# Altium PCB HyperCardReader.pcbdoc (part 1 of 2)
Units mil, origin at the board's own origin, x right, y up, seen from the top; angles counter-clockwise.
Board outline 2181.35 x 1859.05 mil, 2 copper layers (Top Layer, Bottom Layer); 44 components, 43 nets, 186 pads, 102 vias.
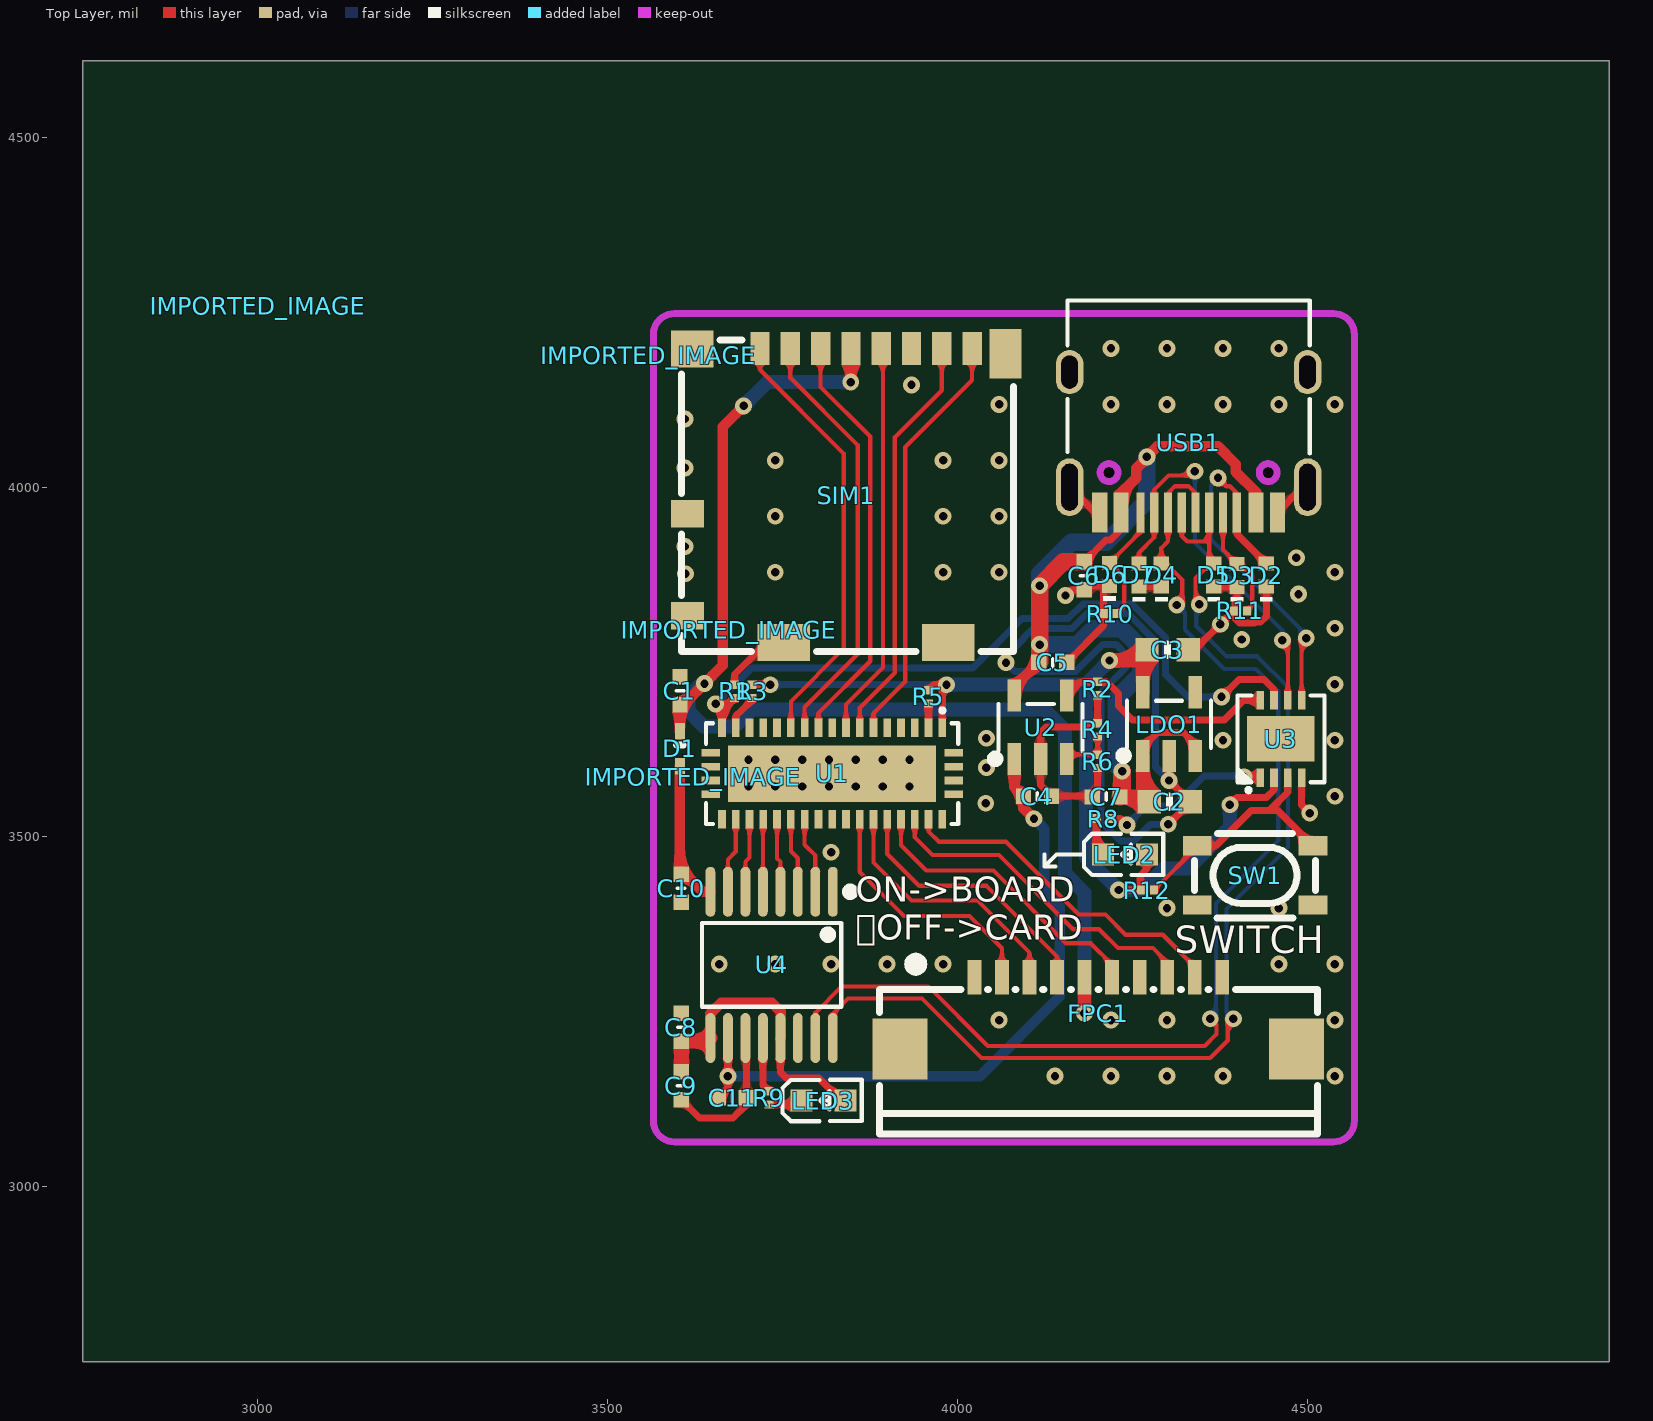
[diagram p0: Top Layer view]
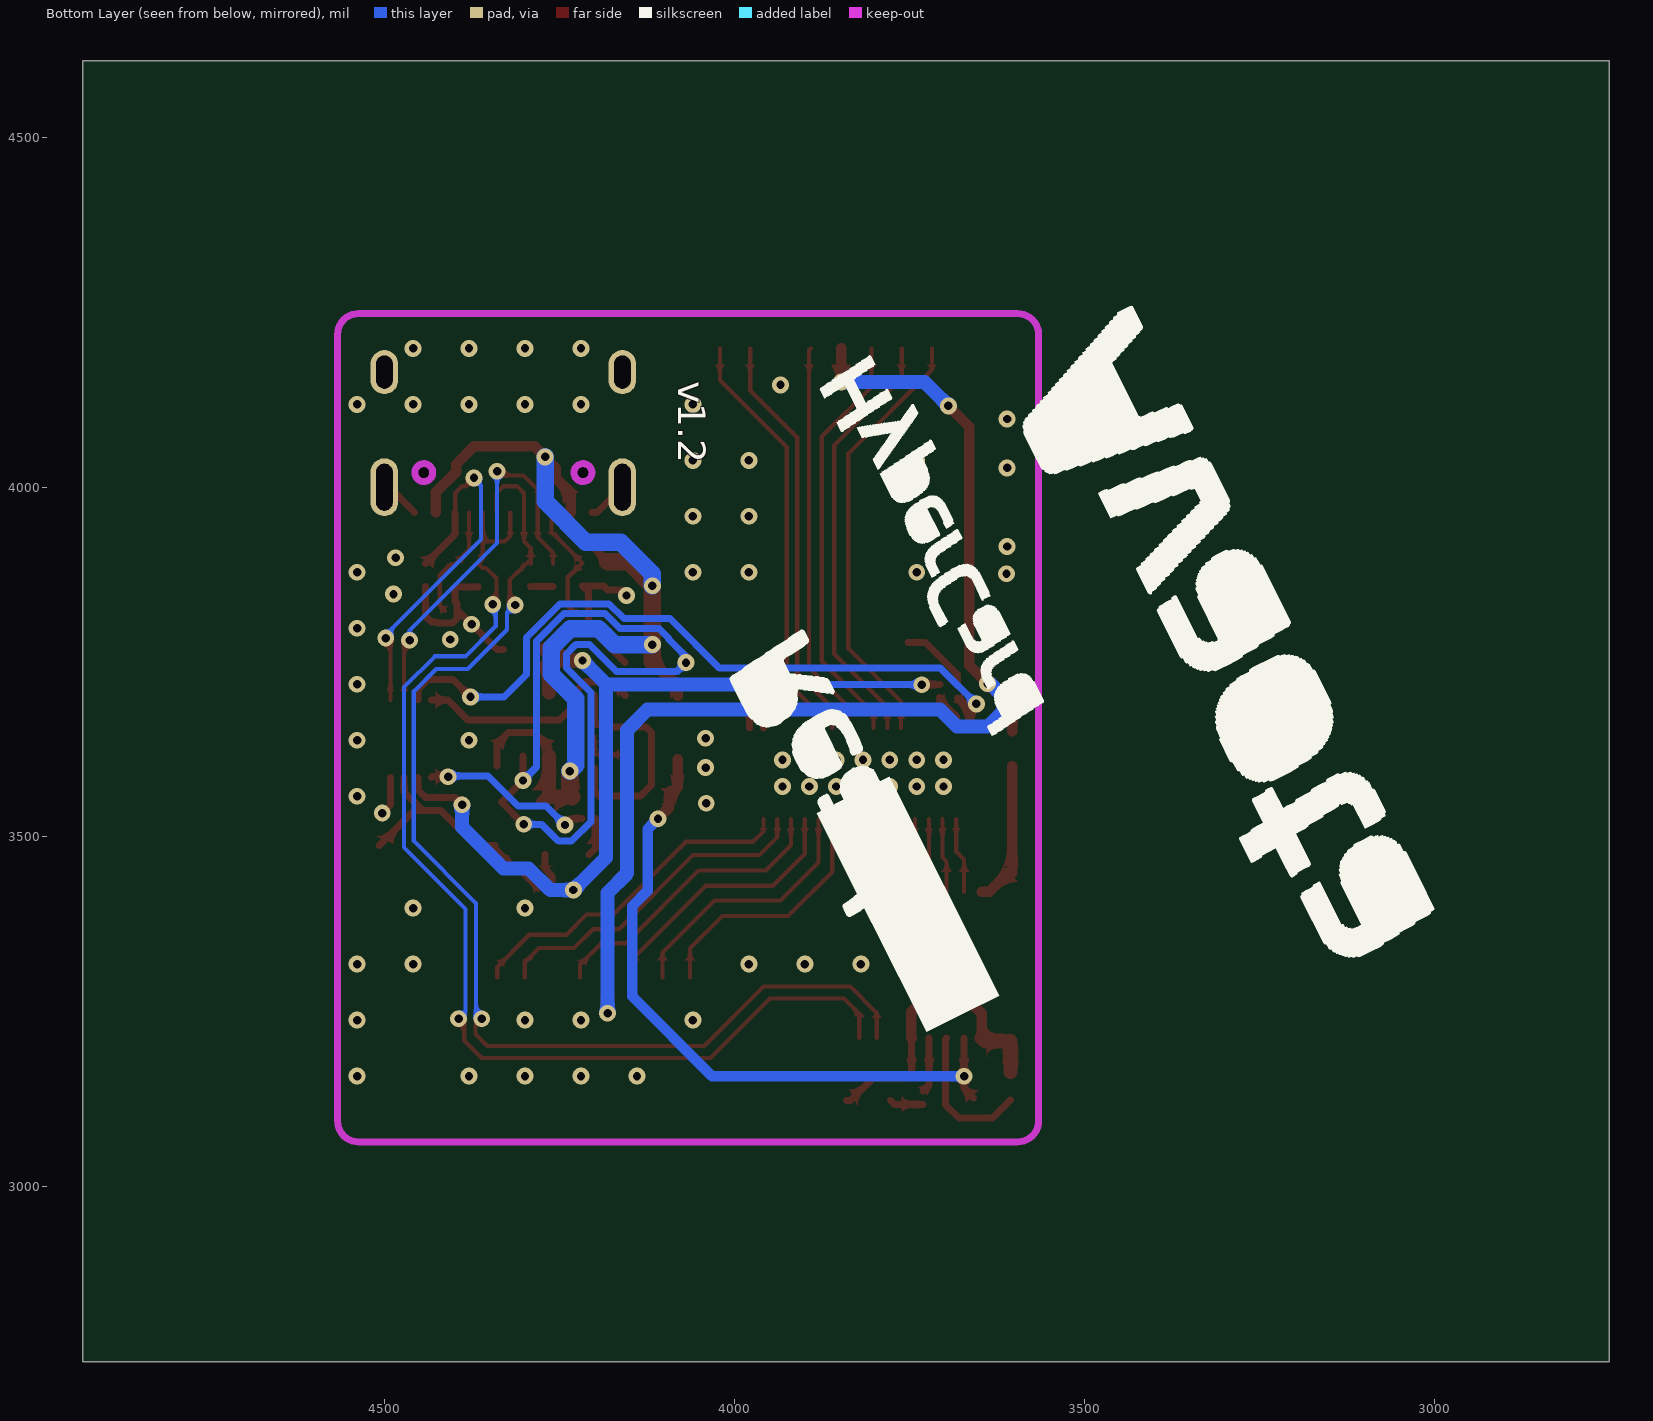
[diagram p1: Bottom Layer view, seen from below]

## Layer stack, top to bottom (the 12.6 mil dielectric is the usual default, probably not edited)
Top Layer: signal copper (thickness not stored)
Dielectric: dielectric 12.6, FR-4, Dk 4.8
Bottom Layer: signal copper (thickness not stored)

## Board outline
4931.35,2750 2750,2750 2750,4609.05 4931.35,4609.05

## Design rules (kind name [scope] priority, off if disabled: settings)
Clearance copperThickness1oz [All] p1: gap=7 ignorepadtopadclearanceinfootprint=FALSE except(4: Track-Track; 6: Track-SMDPad SMDPad-SMDPad Track-THPad SMDPad-THPad THPad-THPad Track-Via SMDPad-Via THPad-Via Via-Via Track-Fill SMDPad-Fill THPad-Fill Via-Fill Fill-Fill SMDPad-Region THPad-Region Via-Region Fill-Region Region-Region Track-Poly SMDPad-Poly THPad-Poly Via-Poly Fill-Poly Poly-Poly Track-Text SMDPad-Text THPad-Text Via-Text Fill-Text Region-Text Poly-Text Text-Text; 6.9: Track-Hole SMDPad-Hole THPad-Hole Via-Hole Fill-Hole Region-Hole Poly-Hole Text-Hole Sheet-Hole; 11.8: Track-Region Region-Poly Track-Sheet SMDPad-Sheet THPad-Sheet Via-Sheet Fill-Sheet Region-Sheet Poly-Sheet Text-Sheet)
Clearance copperThickness2oz [All] p1: gap=7 ignorepadtopadclearanceinfootprint=FALSE except(6: Track-SMDPad SMDPad-SMDPad Track-THPad SMDPad-THPad THPad-THPad Track-Via SMDPad-Via THPad-Via Via-Via Track-Fill SMDPad-Fill THPad-Fill Via-Fill Fill-Fill SMDPad-Region THPad-Region Via-Region Fill-Region Region-Region Track-Poly SMDPad-Poly THPad-Poly Via-Poly Fill-Poly Poly-Poly Track-Text SMDPad-Text THPad-Text Via-Text Fill-Text Region-Text Poly-Text Text-Text; 6.9: Track-Hole SMDPad-Hole THPad-Hole Via-Hole Fill-Hole Region-Hole Poly-Hole Text-Hole Sheet-Hole; 8: Track-Track; 11.8: Track-Region Region-Poly Track-Sheet SMDPad-Sheet THPad-Sheet Via-Sheet Fill-Sheet Region-Sheet Poly-Sheet Text-Sheet)
DiffPairsRouting differentialPair [All] p1: maxuncoupledlength=10 minlimit=0 maxlimit=5.9843 mostfreqgap=5.9843 toplayer_minwidth=5 toplayer_prefwidth=10 toplayer_maxwidth=100 bottomlayer_minwidth=5 bottomlayer_prefwidth=10 bottomlayer_maxwidth=100
PasteMaskExpansion pasteMaskExpansion [All] p1: expansion=0
PlaneConnect innerPlane [All] p1: planeconnectstyle=Relief reliefexpansion=20 reliefentries=4 reliefconductorwidth=10 reliefairgap=10
PolygonConnect copperRegion [All] p1: connectstyle=Relief reliefentries=4 reliefconductorwidth=10 polygonreliefangle="90 Angle" airgapwidth=10
RoutingVias viaSize [All] p1: viastyle="Through Hole" holewidth=12.0078 minholewidth=11.811 maxholewidth=248.0314 width=24.0158 minwidth=19.685 maxwidth=393.7008
SolderMaskExpansion solderMaskExpansion [All] p1: useseparateexpansions=TRUE expansion=2.0079 expansionbottom=2.0079
Width copperThickness1oz [All] p1: maxlimit=100 minlimit=5 preferedwidth=10
Width copperThickness2oz [All] p1: maxlimit=100 minlimit=8 preferedwidth=10

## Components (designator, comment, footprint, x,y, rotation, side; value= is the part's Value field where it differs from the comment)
C1 "CAP_0402" c0402-nsk 3603.35,3709 r270 top
C2 "CAP_0603" C0603-NSK 4303.35,3550 r180 top
C3 "CAP_0603" C0603-NSK 4300.35,3767.54 r180 top
C4 "CAP_0402" c0402-nsk 4114.36,3558.28 r180 top
C5 "CAP_0402" c0402-nsk 4136.36,3749.28 r180 top
C6 "CAP_0402" c0402-nsk 4181.35,3873 r90 top
C7 "CAP_0402" c0402-nsk 4212.35,3557 r0 top
C8 "CAP_0402" c0402-nsk 3605.35,3228 r270 top
C9 "CAP_0402" c0402-nsk 3605.35,3144 r90 top
C10 "CAP_0402" c0402-nsk 3605.25,3426.67 r90 top
C11 "CAP_0402" c0402-nsk 3678.35,3127 r180 top
D1 "B5819WT_C2997265" "SOD-523_L1.2-W0.8-LS1.6-RD-1 NSK" 3603.35,3626 r270 top
D2 "0402ESDA-05N" d0402 4441.35,3874 r90 top
D3 "0402ESDA-05N" d0402 4399.44,3873.72 r90 top
D4 "0402ESDA-05N" d0402 4291.35,3874 r90 top
D5 "0402ESDA-05N" d0402 4366.35,3874 r90 top
D6 "0402ESDA-05N" d0402 4217.35,3875 r90 top
D7 "0402ESDA-05N" d0402 4259.35,3874 r90 top
FPC1 "AFA01-S10FCC-00" FPC-SMD_AFA01-S10FCC-00 4201.35,3248 r0 top
IMPORTED_IMAGE "IMPORTED_IMAGE" IMPORTED_IMAGE 3000,4258.92 r0 top
IMPORTED_IMAGE "IMPORTED_IMAGE" IMPORTED_IMAGE 3557.69,4188.12 r0 top
IMPORTED_IMAGE "IMPORTED_IMAGE" IMPORTED_IMAGE 3621.76,3586.01 r0 top
IMPORTED_IMAGE "IMPORTED_IMAGE" IMPORTED_IMAGE 3672.82,3796.23 r0 top
LDO1 "ME6211C33M5G-N" SOT-23-5_L3.0-W1.7-P0.95-LS2.8-BL 4302.35,3661 r0 top
LED2 "LED_0603-R" LED_0603 4241.35,3475 r0 top
LED3 "LED_0603-R" LED_0603 3810.47,3123.31 r0 top
R1 "Res_0201" "r0201 nsk" 3681.35,3708 r90 top
R2 "Res_0201" "r0201 nsk" 4200.35,3712 r90 top
R3 "Res_0201" "r0201 nsk" 3706.35,3708 r90 top
R4 "Res_0201" "r0201 nsk" 4200.35,3653 r90 top
R5 "Res_0201" "r0201 nsk" 3958.35,3700 r90 top
R6 "Res_0201" "r0201 nsk" 4200.35,3608 r90 top
R8 "Res_0201" "r0201 nsk" 4208.35,3526 r0 top
R9 "Res_0201" "r0201 nsk" 3730.35,3127 r90 top
R10 "Res_0201" "r0201 nsk" 4218.35,3819 r0 top
R11 "Res_0201" "r0201 nsk" 4404.35,3823 r0 top
R12 "Res_0201" "r0201 nsk" 4271.35,3424 r0 top
SIM1 "1040310811" SIM-SMD_8P-1040310811 3841.35,3988 r180 top
SW1 "SKRPACE010" KEY-SMD_4P-L4.2-W3.2-P2.20-LS4.6 4425.35,3445 r0 top
U1 "TS3DV642A0RUAR" WFQFN-42_L9.0-W3.5-P0.50-BL-EP 3821.04,3590.48 r180 top
U2 "SY6280AAC_C55136" SOT-23-5_L3.0-W1.7-P0.95-LS2.8-BL 4118.77,3656.53 r0 top
U3 "STC8G1K08-36I-DFN8" DFN-8_L3.0-W3.0-P0.50-BL-EP 4462.35,3640 r0 top
U4 "GL823K-HCY04" SSOP-16_L4.9-W3.9-P0.64-LS6.0-BL 3734.35,3317 r180 top
USB1 "TYPEC-304-BCP16" USB-C-SMD_TYPEC-304-BCP16-1 4330.35,4064 r180 top

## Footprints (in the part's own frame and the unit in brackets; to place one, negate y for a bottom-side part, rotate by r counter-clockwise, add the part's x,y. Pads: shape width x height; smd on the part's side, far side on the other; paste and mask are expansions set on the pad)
c0402-nsk [mil]
  rect 22x22 smd: 1(-19.99,0) 2(20.01,0)
  silkscreen extent 0,-5 0,6
C0603-NSK [mm]
  rect 0.85x0.85 smd: 1(-0.75,0) 2(0.75,0)
  silkscreen extent 0,-0.21 0,0.21
d0402 [mil]
  rect 19.89x21.68 smd: 1(-16.4,0) 2(16.4,0)
  silkscreen extent -37,-9 -31,9
DFN-8_L3.0-W3.0-P0.50-BL-EP [mm]
  rect 0.28x0.665 smd: 1(-0.75,-1.407) 2(-0.25,-1.407) 3(0.25,-1.407) 4(0.75,-1.407) 5(0.75,1.407) 6(0.25,1.407) 7(-0.25,1.407) 8(-0.75,1.407)
  rect 2.45x1.65 smd: 9(0,0)
  silkscreen extent -1.58,-1.93 1.58,1.58
FPC-SMD_AFA01-S10FCC-00 [mm]
  rect 0.5x1.25 smd: 1(-4.5,1.3) 2(-3.5,1.3) 3(-2.501,1.3) 4(-1.5,1.3) 5(-0.501,1.3) 6(0.499,1.3) 7(1.5,1.3) 8(2.499,1.3) 9(3.5,1.3) 10(4.499,1.3)
  rect 2x2.2 smd: 11(-7.2,-1.3) 12(7.2,-1.3)
  silkscreen extent -7.94,-4.39 7.95,0.86
IMPORTED_IMAGE [mil]
KEY-SMD_4P-L4.2-W3.2-P2.20-LS4.6 [mm]
  rect 1.05x0.7 smd: 1(-2.1,1.075) 2(2.1,1.075) 3(-2.1,-1.075) 4(2.1,-1.075)
  silkscreen extent -2.2,-1.55 2.2,1.52
LED_0603 [mil]
  rect 31.5x31.5 smd: 1(-33.5,-0.4) 2(29.5,-0.2)
  silkscreen extent -61,-30 53,30
"r0201 nsk" [mil]
  rect 11.93x12.76 smd: 1(-9.51,0) 2(9.51,0)
SIM-SMD_8P-1040310811 [mm]
  rect 0.7x1.2 smd: 1(3.138,-5.337) 2(2.037,-5.337) 3(0.938,-5.337) 4(-0.162,-5.337) 5(-1.263,-5.337) 6(-2.363,-5.337) 7(-3.462,-5.337) 8(-4.562,-5.337)
  rect 1.17x1.8 smd: 9(-5.773,-5.138)
  rect 1.55x1.35 smd: 10(5.598,-5.313)
  rect 1.2x1 smd: 11(5.773,0.663) 12(5.773,4.363)
  rect 1.9x1.35 smd: 13(2.273,5.337) 14(-3.697,5.337)
  silkscreen extent -6.07,-5.64 5.99,5.67
"SOD-523_L1.2-W0.8-LS1.6-RD-1 NSK" [mm]
  rect 0.6x0.36 smd: 1(-0.635,0) 2(0.635,0)
  silkscreen extent -0.13,-0.13 -0.13,0.13
SOT-23-5_L3.0-W1.7-P0.95-LS2.8-BL [mm]
  rect 0.49x1.157 smd: 1(-0.95,-1.154) 2(0,-1.154) 3(0.95,-1.154)
  rect 0.49x1.175 smd: 4(0.95,1.154) 5(-0.95,1.154)
  silkscreen extent -1.8,-1.29 1.53,0.85
SSOP-16_L4.9-W3.9-P0.64-LS6.0-BL [mil]
  oval 14x71.45 smd: 1(-87.5,-104.52) 2(-62.5,-104.52) 3(-37.5,-104.52) 4(-12.5,-104.52) 5(12.5,-104.52) 6(37.5,-104.52) 7(62.5,-104.52) 8(87.5,-104.52) 9(87.5,104.52) 10(62.5,104.52) 11(37.5,104.52) 12(12.5,104.52) 13(-12.5,104.52) 14(-37.5,104.52) 15(-62.5,104.52) 16(-87.5,104.52)
  silkscreen extent -118,-110 100,60
USB-C-SMD_TYPEC-304-BCP16-1 [mm]
  oval 1x2.1 hole 0.6 slot 1.7 at 90 deg: 12(-4.32,1.633) 13(4.32,1.633)
  oval 1x1.6 hole 0.6 slot 1.2 at 90 deg: 14(-4.32,-2.547) 15(4.32,-2.547)
  rect 0.55x1.45 smd: A1B12(-3.225,2.547) A4B9(-2.45,2.547) B1A12(3.225,2.547) B4A9(2.45,2.547)
  rect 0.3x1.45 smd: A5(-1.25,2.547) A6(-0.25,2.547) A7(0.25,2.547) A8(1.25,2.547) B5(1.75,2.547) B6(0.75,2.547) B7(-0.75,2.547) B8(-1.75,2.547)
  Multi-Layer board cut-out: -3.215,1.102 -3.169,0.943 -3.051,0.826 -2.89,0.784 -2.729,0.826 -2.611,0.943 -2.565,1.102 -2.565,1.102 -2.611,1.262 -2.729,1.379 -2.89,1.421 -3.051,1.379 -3.169,1.262 -3.215,1.102
  Multi-Layer board cut-out: 2.565,1.102 2.611,0.943 2.729,0.826 2.89,0.784 3.051,0.826 3.169,0.943 3.215,1.102 3.215,1.102 3.169,1.262 3.051,1.379 2.89,1.421 2.729,1.379 2.611,1.262 2.565,1.102
  Multi-Layer keep-out circle w0.254: c-2.89,1.102 r0.325
  Multi-Layer keep-out circle w0.254: c2.89,1.102 r0.325
  silkscreen extent -4.4,-5.15 4.4,0.41
WFQFN-42_L9.0-W3.5-P0.50-BL-EP [mm]
  rect 0.28x0.665 smd: 1(-3.998,-1.658) 2(-3.498,-1.658) 3(-2.998,-1.658) 4(-2.498,-1.658) 5(-1.998,-1.658) 6(-1.498,-1.658) 7(-0.998,-1.658) 8(-0.498,-1.658) 9(0.002,-1.658) 10(0.502,-1.658) 11(1.002,-1.658) 12(1.502,-1.658) 13(2.002,-1.658) 14(2.502,-1.658) 15(3.002,-1.658) 16(3.502,-1.658) 17(4.002,-1.658) 22(4.002,1.658) 23(3.502,1.658) 24(3.002,1.658) 25(2.502,1.658) 26(2.002,1.658) 27(1.502,1.658) 28(1.002,1.658) 29(0.502,1.658) 30(0.002,1.658) 31(-0.498,1.658) 32(-0.998,1.658) 33(-1.498,1.658) 34(-1.998,1.658) 35(-2.498,1.658) 36(-2.998,1.658) 37(-3.498,1.658) 38(-3.998,1.658)
  rect 0.665x0.28 smd: 18(4.41,-0.75) 19(4.41,-0.25) 20(4.41,0.25) 21(4.41,0.75) 39(-4.405,0.75) 40(-4.405,0.25) 41(-4.405,-0.25) 42(-4.405,-0.75)
  rect 7.55x2.05 smd: 43(0.002,0)
  silkscreen extent -4.57,-2.36 4.58,1.83

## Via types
v1: diameter 24.02, hole 12.01, Top Layer to Bottom Layer, 102 vias

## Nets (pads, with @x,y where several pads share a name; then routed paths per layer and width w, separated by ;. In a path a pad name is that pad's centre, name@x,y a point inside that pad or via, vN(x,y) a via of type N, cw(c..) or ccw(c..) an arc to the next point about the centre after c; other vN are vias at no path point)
$1N1961: R4.1 R6.2 U2.3 | length 72.8
  Top Layer w6: U2.3@4156.17,3611.11 4162.57,3617.51 R6.2@4200.35,3617.51 R4.1@4200.35,3643.49
$1N4375: LED3.1 R9.1 | length 48.9
  Top Layer w10: R9.1@3730.35,3117.49 3771.55,3117.49 LED3.1@3776.97,3122.91
$1N4433: LED2.1 R8.1 | length 55.1
  Top Layer w10: R8.1@4198.84,3526 4198.84,3483.61 LED2.1@4207.85,3474.6
CC1: D3.2 R11.2 USB1.A5 | length 164.9
  Top Layer w6: USB1.A5@4379.56,3963.7 4379.56,3910.01 4380.24,3909.33 4380.91,3909.33 4386.18,3904.07 4386.18,3903.39 D3.2@4399.44,3890.12 4405.23,3890.12 4421.35,3874 4421.35,3830.49 R11.2@4413.86,3823
CC2: D6.2 R10.2 USB1.B5 | length 176.4
  Top Layer w6: R10.2@4227.86,3819 4238.35,3829.49 4238.35,3871.09 4231.91,3877.53 4231.22,3877.53 D6.2@4217.35,3891.4 4261.45,3935.5 USB1.B5@4261.45,3963.7
CPUX-RX: D2.2 U3.5 USB1.B8 | length 534.9
  Top Layer w6: v1(4372.35,4013) 4384.12,4001.23 4389.19,4001.23 4399.25,3991.17 USB1.B8@4399.25,3963.7 ; U3.5@4491.88,3695.41 4491.88,3777.53 v1(4498.35,3784)
  Top Layer w10: USB1.B8@4399.25,3963.7 4399.25,3932.5 D2.2@4441.35,3890.4
  Bottom Layer w6: v1(4372.35,4013) 4372.35,4012 4362.35,4002 4362.35,3925 4498.35,3789 v1(4498.35,3784)
CPUX-TX: D7.2 U3.6 USB1.A8 | length 565.8
  Top Layer w6: D7.2@4259.35,3890.4 4259.35,3906 4281.14,3927.79 USB1.A8@4281.14,3963.7 4281.14,3995.79 4301.84,4016.49 4333.38,4016.49 v1(4339.38,4022.49) ; v1(4464.35,3781) 4472.19,3773.16 U3.6@4472.19,3695.41
  Bottom Layer w6: v1(4339.38,4022.49) 4339.35,3920.14 4464.35,3795.14 v1(4464.35,3781)
EN: R5.1 U1.2 | length 34.9
  Top Layer w10: R5.1@3958.35,3690.49 3958.74,3690.1 U1.2@3958.74,3655.74
GND: C1.1 C2.1 C3.1 C4.1 C5.1 C6.1 C7.1 C8.1 C9.1 C10.1 C11.1 D2.1 D3.1 D4.1 D5.1 D6.1 D7.1 FPC1.1 FPC1.7 FPC1.11 FPC1.12 LDO1.2 R1.2 R2.1 R4.2 R6.1 R10.1 R11.1 SIM1.6 SIM1.9 SIM1.10 SIM1.12 SIM1.13 SIM1.14 SW1.3 SW1.4 U1.43 U2.2 U3.4 U3.9 U4.1 U4.11 U4.14 USB1.12 USB1.13 USB1.14 USB1.15 USB1.A1B12 USB1.B1A12 | length 2474.1
  Top Layer w10: C9.1@3605.35,3124.01 3631.36,3098 3679.35,3098 3698.35,3116.99 C11.1@3698.35,3127 3698.35,3210.99 U4.11@3696.85,3212.48 ; R1.2@3681.35,3717.51 3681.35,3732 3727.22,3777.86 SIM1.13@3751.88,3777.86 ; v1(4154.35,3845.01) 4162.35,3853.01 C6.1@4181.35,3853.01 4186.95,3858.6 D6.1@4217.35,3858.6 4208.84,3850.09 R10.1@4208.84,3819 4208.84,3801.77 C5.1@4156.36,3749.28 ; USB1.13@4160.27,3999.72 4196.29,3963.7 USB1.B1A12@4203.38,3963.7 ; R6.1@4200.35,3598.49 4200.35,3564.99 C7.1@4192.36,3557 4191.07,3558.28 C4.1@4134.36,3558.28 4118.77,3573.87 U2.2@4118.77,3611.11 4118.77,3649.42 4126.35,3657 4185.98,3657 4189.42,3660.44 4198.28,3660.44 R4.2@4200.35,3662.51 R2.1@4200.35,3702.49 ; D7.1@4259.35,3857.6 D4.1@4291.35,3857.6 ; v1(4301.35,3518) 4332.88,3549.53 C2.1@4332.88,3550 v1(4302.35,3580.53) LDO1.2@4302.35,3615.58 ; C3.1@4329.88,3767.54 4339.38,3767.54 v1(4375.83,3803.99) R11.1@4394.84,3823 ; D5.1@4366.35,3857.6 4366.63,3857.32 D3.1@4399.44,3857.32 4399.44,3836.46 4396.91,3833.93 4396.91,3825.07 R11.1@4394.84,3823 ; D2.1@4441.35,3857.6 4441.35,3815 4433.35,3807 4425.74,3807 4424.38,3805.64 4403.34,3805.64 4396.91,3812.07 4396.91,3820.93 R11.1@4394.84,3823 ; USB1.A1B12@4457.32,3963.7 4493.34,3999.72 USB1.12@4500.43,3999.72 ; U3.4@4491.88,3584.59 4491.88,3545.47 v1(4503.35,3534)
  Bottom Layer w10: v1(4301.35,3518) 4275.87,3518 4251.87,3494.01 4232.83,3494.01 4205.28,3521.56 4205.28,3706.41 4240.34,3741.48 4240.34,3761.52 4226.87,3774.99 4207.34,3774.99 4168.88,3736.53 4081.82,3736.53 v1(4069.35,3749) 4069.35,3758 4094.36,3783.01 4094.36,3784.31 4107.83,3797.78 4163.71,3797.78 4184.95,3819.02 4243.7,3819.02 4283.37,3779.35 4283.37,3599.5 v1(4302.35,3580.53)
  other v1: 4139.45,3158.1 4219.45,3158.1 4299.45,3158.1 4379.45,3158.1 4539.45,3158.1 4059.45,3238.1 4219.45,3238.1 4299.45,3238.1 4539.45,3238.1 3659.45,3318.1 3739.45,3318.1 3819.45,3318.1 3899.45,3318.1 3979.45,3318.1 4459.45,3318.1 4539.45,3318.1 4299.45,3398.1 4459.45,3398.1 3819.45,3478.1 4040.35,3548 4539.45,3558.1 3701.31,3572 3739.66,3572 3778.01,3572 3816.35,3572 3854.7,3572 3893.04,3572 3931.39,3572 4041.35,3598.98 3701.35,3610 3739.7,3610 3778.04,3610 3816.39,3610 3854.73,3610 3893.08,3610 3931.42,3610 4379.45,3638.1 4539.45,3638.1 4041.35,3641 4539.45,3718.1 4406.35,3782 4539.45,3798.1 4487.35,3847 3611.35,3876 3739.45,3878.1 3979.45,3878.1 4059.45,3878.1 4539.45,3878.1 4484.35,3899 3610.35,3915 3739.45,3958.1 3979.45,3958.1 4059.45,3958.1 3610.35,4027.33 3739.45,4038.1 3979.45,4038.1 4059.45,4038.1 3610.35,4097.22 4059.45,4118.1 4219.45,4118.1 4299.45,4118.1 4379.45,4118.1 4459.45,4118.1 4539.45,4118.1 3934.35,4146 4219.45,4198.1 4299.45,4198.1 4379.45,4198.1 4459.45,4198.1
LED-READ: R9.2 U4.12 | length 79.5
  Top Layer w10: U4.12@3721.85,3212.48 3721.85,3145.01 R9.2@3730.35,3136.51
READ-VCC-EN: R2.2 U2.4 U3.8 | length 329.6
  Top Layer w10: U2.4@4156.17,3701.95 4175.73,3721.51 R2.2@4200.35,3721.51 4213.84,3721.51 4230.35,3705 4230.35,3687 4250.35,3667 4381.35,3667 4409.76,3695.41 U3.8@4432.82,3695.41
SDC-CARD-CLK: SIM1.5 U1.8 | length 565.2
  Top Layer w6: U1.8@3840.63,3655.74 3840.63,3689.28 3893.35,3742 3893.35,4195.84 SIM1.5@3891.06,4198.14
SDC-CARD-CMD: SIM1.3 U1.10 | length 602.5
  Top Layer w6: U1.10@3801.26,3655.74 3801.26,3676.91 3875.35,3751 3875.35,4072 3804.44,4142.91 SIM1.3@3804.44,4198.14
SDC-CARD-D0: SIM1.7 U1.7 | length 591
  Top Layer w6: U1.7@3860.31,3655.74 3860.31,3683.96 3910.35,3734 3910.35,4071 3977.67,4138.31 SIM1.7@3977.67,4198.14
SDC-CARD-D1: SIM1.8 U1.6 | length 600.8
  Top Layer w6: U1.6@3880,3655.74 3880,3676.65 3925.35,3722 3925.35,4057 4020.98,4152.62 SIM1.8@4020.98,4198.14
SDC-CARD-D2: SIM1.1 U1.12 | length 623.2
  Top Layer w6: SIM1.1@3717.83,4198.14 3717.83,4167.52 3837.35,4048 3837.35,3769 3761.89,3693.54 U1.12@3761.89,3655.74
SDC-CARD-D3: SIM1.2 U1.11 | length 613.6
  Top Layer w6: SIM1.2@3761.14,4198.14 3761.14,4156.22 3857.35,4060 3857.35,3761 3781.57,3685.22 U1.11@3781.57,3655.74
SDC-CARD-DET: SIM1.11
SDC-READ-CLK: U1.26 U4.4 | length 105.6
  Top Layer w6: U1.26@3742.2,3525.23 3742.2,3469.15 3746.85,3464.5 U4.4@3746.85,3421.52
SDC-READ-CMD: U1.25 U4.5 | length 104
  Top Layer w6: U4.5@3721.85,3421.52 3721.85,3524.56 U1.25@3722.52,3525.23
SDC-READ-D0: U1.27 U4.3 | length 107.8
  Top Layer w6: U1.27@3761.89,3525.23 3761.89,3479.46 3771.85,3469.5 U4.3@3771.85,3421.52
SDC-READ-D1: U1.28 U4.2 | length 110
  Top Layer w6: U1.28@3781.57,3525.23 3781.57,3488.78 3796.85,3473.5 U4.2@3796.85,3421.52
SDC-READ-D2: U1.23 U4.7 | length 108.4
  Top Layer w6: U4.7@3671.85,3421.52 3671.85,3467.5 3683.15,3478.8 U1.23@3683.15,3525.23
SDC-READ-D3: U1.24 U4.6 | length 106.2
  Top Layer w6: U4.6@3696.85,3421.52 3696.85,3464.5 3702.83,3470.48 U1.24@3702.83,3525.23
SDC-TF-CLK: FPC1.6 U1.35 | length 427.7
  Top Layer w6: U1.35@3919.37,3525.23 3919.37,3487.98 3955.35,3452 4051.35,3452 4155.35,3348 4190.35,3348 4221,3317.36 FPC1.6@4221,3299.19
SDC-TF-CMD: FPC1.4 U1.34 | length 382.8
  Top Layer w6: U1.34@3899.68,3525.23 3899.68,3475.67 3945.35,3430 4041.35,3430 4142.3,3329.05 FPC1.4@4142.3,3299.19
SDC-TF-D0: FPC1.8 U1.36 | length 482.1
  Top Layer w6: U1.36@3939.05,3525.23 3939.05,3499.3 3964.35,3474 4059.35,3474 4165.35,3368 4202.35,3368 4229.35,3341 4279.35,3341 4299.75,3320.61 FPC1.8@4299.75,3299.19
SDC-TF-D1: FPC1.9 U1.37 | length 493.2
  Top Layer w6: U1.37@3958.74,3525.23 3958.74,3507.61 3973.35,3493 4069.35,3493 4173.35,3389 4211.35,3389 4240.35,3360 4293.35,3360 4339.15,3314.2 FPC1.9@4339.15,3299.19
SDC-TF-D2: FPC1.2 U1.32 | length 365.3
  Top Layer w6: U1.32@3860.31,3525.23 3860.31,3450.04 3923.35,3387 4017.35,3387 4063.55,3340.8 FPC1.2@4063.55,3299.19
SDC-TF-D3: FPC1.3 U1.33 | length 373.4
  Top Layer w6: U1.33@3880,3525.23 3880,3463.35 3934.35,3409 4028.35,3409 4102.9,3334.45 FPC1.3@4102.9,3299.19
SDC-TF-DET: FPC1.10
SEL: R1.1 U1.17 U3.7 | length 1038.7
  Top Layer w10: v1(3654.35,3690) 3654.35,3689.71 3663.46,3680.6 ; U1.17@3663.46,3655.74 3663.46,3680.6 ; R1.1@3681.35,3698.49 3663.46,3680.6 ; v1(4377.35,3700) 4402.35,3725 4438.35,3725 4452.51,3710.84 U3.7@4452.51,3695.41
  Bottom Layer w10: v1(3654.35,3690) 3705.35,3741 4021.35,3741 4092.15,3811.8 4157.9,3811.8 4179.14,3833.04 4249.5,3833.04 4297.39,3785.15 4297.39,3731.96 4329.35,3700 v1(4377.35,3700)
SEL1: R3.1 U1.16 | length 54
  Top Layer w10: U1.16@3683.15,3655.74 3683.15,3672.8 3691.89,3681.54 3692.28,3681.54 3698.71,3687.97 3698.71,3688.36 3707.35,3697 R3.1@3707.35,3699.49
SEL1-LED: R8.2 U3.1 | length 248.7
  Top Layer w10: R8.2@4217.86,3526 4233.35,3526 v1(4242.35,3517) ; v1(4409.35,3586) 4431.41,3586 U3.1@4432.82,3584.59
  Bottom Layer w10: v1(4242.35,3517) 4269.35,3544 4309.35,3544 4352.35,3587 4408.35,3587 v1(4409.35,3586)
SEL-BTN: R12.2 SW1.1 SW1.2 U3.3 | length 353.6
  Top Layer w6: R12.2@4280.86,3424 4342.67,3485.81 SW1.1@4342.67,3487.32
  Top Layer w10: SW1.1@4342.67,3487.32 4369.67,3487.32 4420.35,3538 4446.35,3538 ; U3.3@4472.19,3584.59 4472.19,3563.84 4446.35,3538 ; SW1.2@4508.03,3487.32 4457.35,3538 4446.35,3538
USB0-DM: D5.2 U4.16 USB1.A7 USB1.B7 | length 1632.7
  Top Layer w6: U4.16@3821.85,3212.48 3821.85,3247.5 3843.35,3269 3949.35,3269 4034.35,3184 4361.35,3184 4386.35,3209 4386.35,3232 v1(4394.35,3240) ; USB1.A7@4320.51,3963.7 4320.51,3929.84 4328.35,3922 4352.22,3922 4359.88,3929.66 ; v1(4345.53,3832.18) 4340.35,3837.37 4340.35,3869.62 4355.13,3884.4 4360.35,3884.4 D5.2@4366.35,3890.4 4359.88,3896.87 4359.88,3929.66 ; USB1.B7@4359.88,3963.7 4359.88,3929.66
  Bottom Layer w6: v1(4345.53,3832.18) 4341.35,3828 4341.35,3801 4384.35,3758 4428.35,3758 4472.35,3714 4472.35,3485 4384.35,3397 4384.35,3250 v1(4394.35,3240)
USB0-DP: D4.2 U4.15 USB1.A6 USB1.B6 | length 1672.6
  Top Layer w6: U4.15@3796.85,3212.48 3796.85,3248.5 3834.35,3286 3958.35,3286 4043.35,3201 4353.35,3201 4370.35,3218 4370.35,3231 v1(4361.35,3240) ; v1(4313.36,3831.38) 4321.35,3839.37 4321.35,3867 4294.65,3893.7 D4.2@4291.35,3890.4 4291.35,3913 4300.82,3922.47 USB1.B6@4300.82,3963.7 4300.82,3991.17 4310.88,4001.23 4330.14,4001.23 4340.19,3991.18 USB1.A6@4340.19,3963.7
  Bottom Layer w6: v1(4313.36,3831.38) 4313.97,3831.38 4325.35,3820 4325.35,3796 4381.35,3740 4426.35,3740 4458.35,3708 4458.35,3494 4369.35,3405 4369.35,3248 v1(4361.35,3240)
VBUS-USB: C2.2 C5.2 C6.2 C7.2 LDO1.1 LDO1.3 U2.5 USB1.A4B9 USB1.B4A9 | length 1578.1
  Top Layer w10: C6.2@4181.35,3893.01 4212.52,3924.18 4218.76,3924.18 4233.89,3939.31 USB1.B4A9@4233.89,3963.7 ; LDO1.1@4264.95,3615.58 4264.95,3628.6 4285.69,3649.34 4323.01,3649.34 4339.75,3632.6 LDO1.3@4339.75,3601.6
  Top Layer w15: U2.5@4081.37,3701.95 4081.37,3714.3 C5.2@4116.36,3749.28 ; USB1.B4A9@4233.89,3963.7 4233.89,3991.54 4255.86,4013.51 4255.86,4026.56 4270.71,4041.41 v1(4270.71,4043) 4285.71,4058 4372.35,4058 4397.84,4032.51 4397.84,4021.48 4426.81,3992.51 USB1.A4B9@4426.81,3963.7
  Top Layer w20: C7.2@4232.36,3557 C2.2@4266.82,3557 ; LDO1.1@4264.95,3615.58 4264.95,3558.87 C2.2@4266.82,3557 ; C2.2@4273.82,3550 C2.2@4266.82,3557
  Top Layer w25: C5.2@4116.36,3749.28 4117.36,3750.28 v1(4117.36,3774.79) v1(4117.36,3859.01) 4151.36,3893.01 C6.2@4181.35,3893.01 ; C7.2@4232.36,3557 4235.35,3559.99 v1(4235.35,3594)
  Bottom Layer w25: v1(4117.36,3774.79) 4171.14,3774.79 4193.86,3797.51 4234.79,3797.51 4261.86,3770.44 4261.86,3732.56 4226.79,3697.5 4226.79,3602.56 v1(4235.35,3594) ; v1(4117.36,3859.01) 4117.36,3876.01 4162.35,3921 4212.35,3921 4270.71,3979.36 v1(4270.71,4043)
VCC-3V3-CARD: C10.2 D1.2 U4.8 | length 212.1
  Top Layer w15: D1.2@3603.35,3601 C10.2@3603.35,3454 ; C10.2@3605.25,3446.68 3603.35,3448.58 C10.2@3603.35,3454 ; U4.8@3646.85,3421.52 3635.83,3421.52 C10.2@3603.35,3454
VCC-3V3-LDO: C3.2 LDO1.5 LED2.2 R3.2 R5.2 R12.1 U1.1 U3.2 | length 1451.4
  Top Layer w10: R3.2@3706.35,3717.51 v1(3732.35,3717.51) ; R5.2@3958.35,3709.51 3966.35,3717.51 v1(3984.35,3717.51) 3978.42,3711.58 U1.1@3978.42,3655.74 ; v1(4230.35,3424) R12.1@4261.84,3424 4261.35,3424.49 4261.35,3445 4270.85,3454.5 LED2.2@4270.85,3474.8 ; v1(4389.35,3546) 4399.35,3556 4441.35,3556 4452.51,3567.16 U3.2@4452.51,3584.59
  Top Layer w20: v1(4217.35,3752) 4255.29,3752 C3.2@4264.95,3761.66 ; LDO1.5@4264.95,3706.42 C3.2@4264.95,3761.66 ; C3.2@4270.82,3767.54 C3.2@4264.95,3761.66
  Bottom Layer w10: v1(3732.35,3717.51) v1(3984.35,3717.51)
  Bottom Layer w20: v1(3984.35,3717.51) 4183.86,3717.51 ; v1(4217.35,3752) 4183.86,3718.51 4183.86,3717.51 ; v1(4389.35,3546) 4389.35,3514 4330.35,3455 4294.35,3455 4263.35,3424 v1(4230.35,3424) 4183.86,3470.49 4183.86,3717.51
VCC-CARD: C1.2 D1.1 FPC1.5 SIM1.4 | length 1808.9
  Top Layer w15: D1.1@3603.35,3651 C1.2@3603.35,3688.99 3608.35,3688.99 v1(3638.38,3719.02) 3664.35,3745 3664.35,4086 v1(3694.35,4116) ; v1(3847.35,4150) 3847.75,4150.4 SIM1.4@3847.75,4198.14
  Top Layer w18: v1(4181.35,3248) 4181.65,3248.3 FPC1.5@4181.65,3299.19
  Bottom Layer w20: v1(3638.38,3719.02) 3634.38,3719.02 3615.35,3700 3615.35,3680 3637.35,3658 3682.35,3658 3706.35,3682 4124.35,3682 4153.35,3653 4153.35,3448 4181.35,3420 v1(4181.35,3248) ; v1(3694.35,4116) 3728.35,4150 v1(3847.35,4150)
VCC-READ: C4.2 C11.2 U2.1 U4.10 | length 978.9
  Top Layer w10: C11.2@3658.35,3127 3671.85,3140.51 v1(3671.85,3157.8) U4.10@3671.85,3212.48
  Top Layer w15: U2.1@4081.37,3611.11 4081.37,3571.27 C4.2@4094.36,3558.28 4094.36,3540.99 v1(4109.35,3526)
  Bottom Layer w15: v1(3671.85,3157.8) 4032.15,3157.8 4146.35,3272 4146.35,3401 4124.35,3423 4124.35,3511 v1(4109.35,3526)
VDD-3V3: C8.2 C9.2 LED3.2 U4.9 U4.13 | length 431.2
  Top Layer w10: U4.13@3746.85,3212.48 3746.85,3163.5 3755.35,3155 3802.35,3155 3834.24,3123.11 LED3.2@3839.97,3123.11
  Top Layer w15: U4.9@3646.85,3212.48 3646.85,3247.5 3662.35,3263 3734.35,3263 3747.35,3250 3747.35,3212.98 U4.13@3746.85,3212.48
  Top Layer w20: C9.2@3605.35,3164.01 C8.2@3605.35,3207.99 3642.37,3207.99 U4.9@3646.85,3212.48
pads on no net: LDO1.4 U1.3 U1.4 U1.5 U1.9 U1.13 U1.14 U1.15 U1.18 U1.19 U1.20 U1.21 U1.22 U1.29 U1.30 U1.31 U1.38 U1.39 U1.40 U1.41 U1.42

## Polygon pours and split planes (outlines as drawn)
GND on Top Layer (solid, remove dead copper, pour order 0): 3474.35,3000 4681.35,3000 4681.35,4338 3474.35,4338
GND on Bottom Layer (solid, remove dead copper, pour order 2): 3455.18,3021.05 4662.18,3021.05 4662.18,4359.05 3455.18,4359.05

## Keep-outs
Board Outline Layer:
  lines w10: 3565.35,3094 ccw(c3595.35,3094) 3595.35,3064 4537.35,3064 ccw(c4537.35,3094) 4567.35,3094 4567.35,4218 ccw(c4537.35,4218) 4537.35,4248 3595.35,4248 ccw(c3595.35,4218) 3565.35,4218 3565.35,3094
